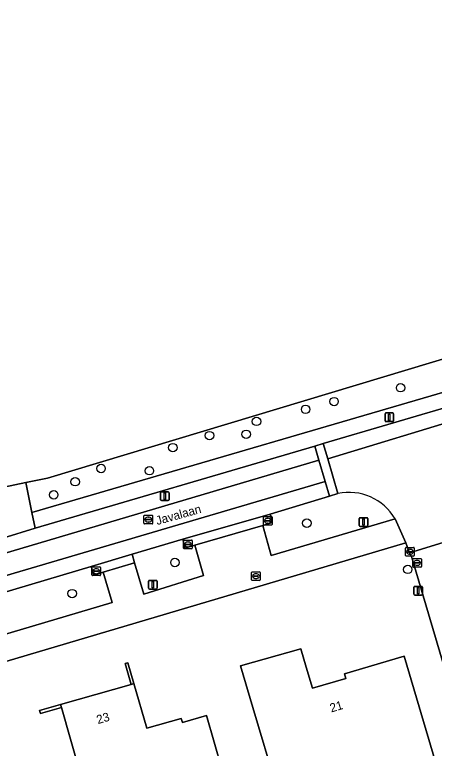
# Model space of a CAD drawing. Extents: x 162417 to 163722, y 384268 to 385417.
# Drawn here: x 163254.9 to 163303.2, y 384656 to 384740.4 of the extents above; entities that cross this region are included whole.
import ezdxf

# ---------------------------------------------------------------- set-up
doc = ezdxf.new("R2010")
doc.units = 0
for name, color, linetype in [('IMGEO_Boom', 7, 'Continuous'), ('IMGEO_Brandkraan', 7, 'Continuous'), ('IMGEO_Erf', 7, 'Continuous'), ('IMGEO_Groenvoorziening', 7, 'Continuous'), ('IMGEO_Kolk', 7, 'Continuous'), ('IMGEO_Lichtmast', 7, 'Continuous'), ('IMGEO_Muur', 7, 'Continuous'), ('IMGEO_Openbare_ruimte_label', 7, 'Continuous'), ('IMGEO_Pand', 7, 'Continuous'), ('IMGEO_Pand_nummerreeks', 7, 'Continuous'), ('IMGEO_Rijbaan_lokaal_gesloten', 7, 'Continuous'), ('IMGEO_Rijbaan_lokaal_open', 7, 'Continuous'), ('IMGEO_Rioolput', 7, 'Continuous'), ('IMGEO_Voetpad_open', 7, 'Continuous')]:
    doc.layers.add(name, color=color, linetype=linetype)

msp = doc.modelspace()

# ---------------------------------------------------------------- linework, layer by layer
at = {"layer": 'IMGEO_Boom'}
for centre in [(163299.34, 384697.477), (163291.666, 384695.87), (163288.39, 384694.985), (163282.725, 384693.6), (163281.545, 384692.108), (163277.309, 384691.956), (163273.098, 384690.574), (163264.817, 384688.168), (163270.393, 384687.917), (163261.835, 384686.655), (163259.364, 384685.138), (163288.537, 384681.888), (163273.332, 384677.355), (163300.151, 384676.563), (163261.491, 384673.768)]:
    msp.add_circle(centre, 0.489, dxfattribs=at)
at = {"layer": 'IMGEO_Brandkraan'}
for p, q in [((163282.16, 384675.355), (163282.16, 384676.207)), ((163282.235, 384676.281), (163283.087, 384676.281)), ((163282.419, 384675.775), (163282.419, 384675.787)), ((163282.857, 384675.738), (163282.459, 384675.738)), ((163282.462, 384675.824), (163282.86, 384675.824)), ((163282.648, 384676.061), (163282.673, 384676.061)), ((163282.903, 384675.787), (163282.903, 384675.775)), ((163283.161, 384676.207), (163283.161, 384675.355)), ((163283.087, 384675.281), (163282.235, 384675.281)), ((163282.671, 384675.501), (163282.646, 384675.501))]:
    msp.add_line(p, q, dxfattribs=at)
for points in [[(163282.16, 384675.355), (163282.16, 384676.207)], [(163282.235, 384676.281), (163283.087, 384676.281)], [(163283.161, 384676.207), (163283.161, 384675.355)], [(163283.087, 384675.281), (163282.235, 384675.281)]]:
    msp.add_lwpolyline(points, dxfattribs=at)
for centre, radius, start, end in [((163282.237, 384676.205), 0.0765, 91.55205, 178.44795), ((163282.237, 384676.205), 0.0765, 91.55205, 178.44795), ((163282.459, 384675.784), 0.0403, 85.87752, 175.75265), ((163282.456, 384675.774), 0.0366, 178.93798, 274.71019), ((163282.86, 384675.781), 0.043, 264.86636, 352.45326), ((163282.864, 384675.786), 0.0386, 1.73085, 96.63898), ((163283.085, 384676.205), 0.0765, 1.55205, 88.44795), ((163283.085, 384676.205), 0.0765, 1.55205, 88.44795), ((163282.237, 384675.357), 0.0765, 181.55205, 268.44795), ((163282.237, 384675.357), 0.0765, 181.55205, 268.44795), ((163283.085, 384675.357), 0.0765, 271.55205, 358.44795), ((163283.085, 384675.357), 0.0765, 271.55205, 358.44795)]:
    msp.add_arc(centre, radius, start, end, dxfattribs=at)
for centre, major_axis, ratio, start_param, end_param in [((163282.647, 384675.781), (-0.387, 0.002), 0.722429, 4.712389, 7.853982), ((163282.672, 384675.781), (-0.39, 0.002), 0.717154, 1.570796, 4.712389)]:
    msp.add_ellipse(centre, major_axis=major_axis, ratio=ratio, start_param=start_param, end_param=end_param, dxfattribs=at)
at = {"layer": 'IMGEO_Erf'}
for points in [[(163175.984, 384894.871), (163189.317, 384805.604), (163189.37, 384805.252), (163225.47, 384820.661), (163226.246, 384820.995), (163226.612, 384820.203), (163229.945, 384812.987), (163225.751, 384811.048), (163227.566, 384807.013), (163229.658, 384807.895), (163230.655, 384805.678), (163228.563, 384804.796), (163224.144, 384802.92), (163192.437, 384789.411), (163200.664, 384750), (163215.633, 384678.291), (163252.312, 384685.775), (163256.147, 384686.557), (163258.646, 384687.067), (163309.002, 384702.202), (163311.14, 384702.845), (163432.284, 384738.586)], [(163310.764, 384635.802), (163312.926, 384636.415), (163300.634, 384677.935), (163300.352, 384678.47), (163299.946, 384679.602), (163217.164, 384655.09), (163211.589, 384653.439), (163162.154, 384638.801), (163163.733, 384633.465), (163163.883, 384632.961), (163162.442, 384632.589), (163160.726, 384632.111), (163162.281, 384626.769), (163162.11, 384626.271), (163182.33, 384558.292), (163182.739, 384554.615), (163182.929, 384552.906)]]:
    msp.add_lwpolyline(points, dxfattribs=at)
for points in [[(163288.704, 384650.731), (163289.155, 384649.207), (163289.279, 384648.786), (163285.109, 384647.551), (163284.023, 384651.221), (163285.022, 384651.517), (163282.318, 384660.655), (163280.899, 384665.449), (163287.845, 384667.428), (163288.469, 384665.32), (163289.195, 384662.869), (163293.012, 384663.999), (163292.855, 384664.526), (163299.758, 384666.57), (163306.744, 384642.968), (163301.95, 384641.549), (163299.749, 384640.897), (163296.634, 384651.421), (163296.183, 384652.945)], [(163260.25, 384660.667), (163257.838, 384659.974), (163257.742, 384660.3), (163260.157, 384660.994), (163268.278, 384663.328), (163267.585, 384665.72), (163267.913, 384665.805), (163268.6, 384663.42), (163270.078, 384658.288), (163274.054, 384659.406), (163274.19, 384658.922), (163276.954, 384659.724), (163280.51, 384647.464), (163277.235, 384646.514), (163276.473, 384649.14), (163270.819, 384647.5), (163270.801, 384647.562), (163264.63, 384645.772), (163264.607, 384645.854), (163264.482, 384645.818)]]:
    msp.add_lwpolyline(points, close=True, dxfattribs=at)
at = {"layer": 'IMGEO_Groenvoorziening'}
for points in [[(163434.845, 384735.97), (163434.107, 384738.766), (163432.394, 384738.238), (163432.284, 384738.586), (163311.14, 384702.845), (163309.002, 384702.202), (163258.646, 384687.067), (163256.147, 384686.557), (163256.857, 384683.119), (163311.275, 384698.988), (163310.335, 384702.113), (163313.232, 384702.984), (163314.169, 384699.824)], [(163289.436, 384690.763), (163290.424, 384691.053), (163306.618, 384695.814), (163307.647, 384696.083), (163311.775, 384697.325), (163311.275, 384698.988), (163256.857, 384683.119), (163257.233, 384681.296)], [(163275.63, 384679.354), (163274.478, 384678.992), (163274.226, 384680.026), (163268.396, 384678.308), (163268.691, 384677.315), (163269.763, 384673.71), (163276.632, 384675.863)], [(163266.1, 384672.742), (163265.056, 384676.225), (163263.975, 384675.897), (163263.667, 384676.895), (163247.767, 384672.179), (163248.057, 384671.212), (163249.111, 384667.719)]]:
    msp.add_lwpolyline(points, close=True, dxfattribs=at)
msp.add_lwpolyline([(163292.104, 384685.298), (163291.154, 384684.983), (163284.314, 384682.93), (163284.533, 384681.94), (163283.462, 384681.623), (163284.428, 384678.165), (163298.709, 384682.365)], dxfattribs=at)
msp.add_arc((163293.368, 384679.241), 6.188, 30.32681, 101.78524, dxfattribs=at)
at = {"layer": 'IMGEO_Kolk'}
for p, q in [((163283.528, 384681.735), (163283.528, 384682.587)), ((163283.603, 384682.661), (163284.455, 384682.661)), ((163284.016, 384682.441), (163284.041, 384682.441)), ((163284.529, 384682.587), (163284.529, 384681.735)), ((163284.455, 384681.661), (163283.603, 384681.661)), ((163283.787, 384682.155), (163283.787, 384682.167)), ((163284.225, 384682.118), (163283.827, 384682.118)), ((163283.83, 384682.204), (163284.228, 384682.204)), ((163284.039, 384681.881), (163284.014, 384681.881)), ((163284.271, 384682.167), (163284.271, 384682.155)), ((163274.404, 384679.936), (163275.256, 384679.936)), ((163274.329, 384679.01), (163274.329, 384679.862)), ((163274.588, 384679.43), (163274.588, 384679.442)), ((163275.026, 384679.393), (163274.628, 384679.393)), ((163274.631, 384679.479), (163275.029, 384679.479)), ((163274.84, 384679.156), (163274.815, 384679.156)), ((163274.817, 384679.716), (163274.842, 384679.716)), ((163275.072, 384679.442), (163275.072, 384679.43)), ((163275.33, 384679.862), (163275.33, 384679.01)), ((163299.987, 384679.094), (163300.839, 384679.094)), ((163275.256, 384678.936), (163274.404, 384678.936)), ((163299.912, 384678.168), (163299.912, 384679.02)), ((163300.171, 384678.588), (163300.171, 384678.6)), ((163300.609, 384678.551), (163300.211, 384678.551)), ((163300.214, 384678.637), (163300.612, 384678.637)), ((163300.423, 384678.314), (163300.398, 384678.314)), ((163300.4, 384678.874), (163300.425, 384678.874)), ((163300.655, 384678.6), (163300.655, 384678.588)), ((163300.913, 384679.02), (163300.913, 384678.168)), ((163300.839, 384678.094), (163299.987, 384678.094)), ((163263.764, 384675.916), (163263.764, 384676.768)), ((163263.839, 384676.842), (163264.691, 384676.842)), ((163264.252, 384676.622), (163264.277, 384676.622)), ((163264.765, 384676.768), (163264.765, 384675.916)), ((163264.691, 384675.842), (163263.839, 384675.842)), ((163264.023, 384676.336), (163264.023, 384676.348)), ((163264.461, 384676.299), (163264.063, 384676.299)), ((163264.066, 384676.385), (163264.464, 384676.385)), ((163264.275, 384676.062), (163264.25, 384676.062)), ((163264.507, 384676.348), (163264.507, 384676.336))]:
    msp.add_line(p, q, dxfattribs=at)
for points in [[(163283.528, 384681.735), (163283.528, 384682.587)], [(163283.603, 384682.661), (163284.455, 384682.661)], [(163284.529, 384682.587), (163284.529, 384681.735)], [(163284.455, 384681.661), (163283.603, 384681.661)], [(163274.404, 384679.936), (163275.256, 384679.936)], [(163274.329, 384679.01), (163274.329, 384679.862)], [(163275.33, 384679.862), (163275.33, 384679.01)], [(163299.987, 384679.094), (163300.839, 384679.094)], [(163275.256, 384678.936), (163274.404, 384678.936)], [(163299.912, 384678.168), (163299.912, 384679.02)], [(163300.913, 384679.02), (163300.913, 384678.168)], [(163300.839, 384678.094), (163299.987, 384678.094)], [(163263.764, 384675.916), (163263.764, 384676.768)], [(163263.839, 384676.842), (163264.691, 384676.842)], [(163264.765, 384676.768), (163264.765, 384675.916)], [(163264.691, 384675.842), (163263.839, 384675.842)]]:
    msp.add_lwpolyline(points, dxfattribs=at)
for centre, radius, start, end in [((163283.605, 384682.585), 0.0765, 91.55205, 178.44795), ((163283.605, 384682.585), 0.0765, 91.55205, 178.44795), ((163284.453, 384682.585), 0.0765, 1.55205, 88.44795), ((163284.453, 384682.585), 0.0765, 1.55205, 88.44795), ((163283.605, 384681.737), 0.0765, 181.55205, 268.44795), ((163283.605, 384681.737), 0.0765, 181.55205, 268.44795), ((163283.827, 384682.164), 0.0403, 85.87752, 175.75265), ((163283.824, 384682.154), 0.0366, 178.93798, 274.71019), ((163284.228, 384682.161), 0.043, 264.86636, 352.45326), ((163284.232, 384682.166), 0.0386, 1.73085, 96.63898), ((163284.453, 384681.737), 0.0765, 271.55205, 358.44795), ((163284.453, 384681.737), 0.0765, 271.55205, 358.44795), ((163274.406, 384679.86), 0.0765, 91.55205, 178.44795), ((163274.406, 384679.86), 0.0765, 91.55205, 178.44795), ((163275.254, 384679.86), 0.0765, 1.55205, 88.44795), ((163275.254, 384679.86), 0.0765, 1.55205, 88.44795), ((163274.628, 384679.439), 0.0403, 85.87752, 175.75265), ((163274.625, 384679.429), 0.0366, 178.93798, 274.71019), ((163275.029, 384679.436), 0.043, 264.86636, 352.45326), ((163275.033, 384679.441), 0.0386, 1.73085, 96.63898), ((163299.989, 384679.018), 0.0765, 91.55205, 178.44795), ((163299.989, 384679.018), 0.0765, 91.55205, 178.44795), ((163300.837, 384679.018), 0.0765, 1.55205, 88.44795), ((163300.837, 384679.018), 0.0765, 1.55205, 88.44795), ((163274.406, 384679.012), 0.0765, 181.55205, 268.44795), ((163274.406, 384679.012), 0.0765, 181.55205, 268.44795), ((163275.254, 384679.012), 0.0765, 271.55205, 358.44795), ((163275.254, 384679.012), 0.0765, 271.55205, 358.44795), ((163300.211, 384678.597), 0.0403, 85.87752, 175.75265), ((163300.208, 384678.587), 0.0366, 178.93798, 274.71019), ((163300.612, 384678.594), 0.043, 264.86636, 352.45326), ((163300.616, 384678.599), 0.0386, 1.73085, 96.63898), ((163299.989, 384678.17), 0.0765, 181.55205, 268.44795), ((163299.989, 384678.17), 0.0765, 181.55205, 268.44795), ((163300.837, 384678.17), 0.0765, 271.55205, 358.44795), ((163300.837, 384678.17), 0.0765, 271.55205, 358.44795), ((163263.841, 384676.766), 0.0765, 91.55205, 178.44795), ((163263.841, 384676.766), 0.0765, 91.55205, 178.44795), ((163264.689, 384676.766), 0.0765, 1.55205, 88.44795), ((163264.689, 384676.766), 0.0765, 1.55205, 88.44795), ((163263.841, 384675.918), 0.0765, 181.55205, 268.44795), ((163263.841, 384675.918), 0.0765, 181.55205, 268.44795), ((163264.063, 384676.345), 0.0403, 85.87752, 175.75265), ((163264.06, 384676.335), 0.0366, 178.93798, 274.71019), ((163264.464, 384676.342), 0.043, 264.86636, 352.45326), ((163264.468, 384676.347), 0.0386, 1.73085, 96.63898), ((163264.689, 384675.918), 0.0765, 271.55205, 358.44795), ((163264.689, 384675.918), 0.0765, 271.55205, 358.44795)]:
    msp.add_arc(centre, radius, start, end, dxfattribs=at)
for centre, major_axis, ratio, start_param, end_param in [((163284.015, 384682.161), (-0.387, 0.002), 0.722429, 4.712389, 7.853982), ((163284.04, 384682.161), (-0.39, 0.002), 0.717154, 1.570796, 4.712389), ((163274.816, 384679.436), (-0.387, 0.002), 0.722429, 4.712389, 7.853982), ((163274.841, 384679.436), (-0.39, 0.002), 0.717154, 1.570796, 4.712389), ((163300.399, 384678.594), (-0.387, 0.002), 0.722429, 4.712389, 7.853982), ((163300.424, 384678.594), (-0.39, 0.002), 0.717154, 1.570796, 4.712389), ((163264.251, 384676.342), (-0.387, 0.002), 0.722429, 4.712389, 7.853982), ((163264.276, 384676.342), (-0.39, 0.002), 0.717154, 1.570796, 4.712389)]:
    msp.add_ellipse(centre, major_axis=major_axis, ratio=ratio, start_param=start_param, end_param=end_param, dxfattribs=at)
at = {"layer": 'IMGEO_Lichtmast'}
for p, q in [((163297.537, 384693.672), (163297.537, 384694.472)), ((163297.537, 384694.472), (163297.537, 384693.672)), ((163297.637, 384694.572), (163298.427, 384694.572)), ((163298.427, 384694.572), (163297.637, 384694.572)), ((163298.527, 384694.472), (163298.527, 384693.672)), ((163298.527, 384693.672), (163298.527, 384694.472)), ((163298.427, 384693.572), (163297.637, 384693.572)), ((163297.637, 384693.572), (163298.427, 384693.572)), ((163271.667, 384684.583), (163271.667, 384685.383)), ((163271.667, 384685.383), (163271.667, 384684.583)), ((163271.767, 384685.483), (163272.557, 384685.483)), ((163272.557, 384685.483), (163271.767, 384685.483)), ((163272.657, 384685.383), (163272.657, 384684.583)), ((163272.657, 384684.583), (163272.657, 384685.383)), ((163272.557, 384684.483), (163271.767, 384684.483)), ((163271.767, 384684.483), (163272.557, 384684.483)), ((163294.677, 384682.511), (163295.467, 384682.511)), ((163295.467, 384682.511), (163294.677, 384682.511)), ((163294.577, 384681.611), (163294.577, 384682.411)), ((163294.577, 384682.411), (163294.577, 384681.611)), ((163295.567, 384682.411), (163295.567, 384681.611)), ((163295.567, 384681.611), (163295.567, 384682.411)), ((163295.467, 384681.511), (163294.677, 384681.511)), ((163294.677, 384681.511), (163295.467, 384681.511)), ((163270.293, 384674.4), (163270.293, 384675.2)), ((163270.293, 384675.2), (163270.293, 384674.4)), ((163270.393, 384675.3), (163271.183, 384675.3)), ((163271.183, 384675.3), (163270.393, 384675.3)), ((163271.283, 384675.2), (163271.283, 384674.4)), ((163271.283, 384674.4), (163271.283, 384675.2)), ((163271.183, 384674.3), (163270.393, 384674.3)), ((163270.393, 384674.3), (163271.183, 384674.3)), ((163300.87, 384673.709), (163300.87, 384674.509)), ((163300.87, 384674.509), (163300.87, 384673.709)), ((163300.97, 384674.609), (163301.76, 384674.609)), ((163301.76, 384674.609), (163300.97, 384674.609)), ((163301.86, 384674.509), (163301.86, 384673.709)), ((163301.86, 384673.709), (163301.86, 384674.509)), ((163301.76, 384673.609), (163300.97, 384673.609)), ((163300.97, 384673.609), (163301.76, 384673.609))]:
    msp.add_line(p, q, dxfattribs=at)
for points in [[(163297.957, 384694.447), (163298.107, 384694.447), (163298.107, 384693.697), (163297.957, 384693.697), (163297.957, 384694.447)], [(163272.087, 384685.358), (163272.237, 384685.358), (163272.237, 384684.608), (163272.087, 384684.608), (163272.087, 384685.358)], [(163294.997, 384682.386), (163295.147, 384682.386), (163295.147, 384681.636), (163294.997, 384681.636), (163294.997, 384682.386)], [(163270.713, 384675.175), (163270.863, 384675.175), (163270.863, 384674.425), (163270.713, 384674.425), (163270.713, 384675.175)], [(163301.29, 384674.484), (163301.44, 384674.484), (163301.44, 384673.734), (163301.29, 384673.734), (163301.29, 384674.484)]]:
    msp.add_lwpolyline(points, dxfattribs=at)
for centre, start, end in [((163297.637, 384694.472), 90, 180), ((163297.637, 384694.472), 90, 180), ((163298.427, 384694.472), 0, 90), ((163298.427, 384694.472), 360, 90), ((163297.637, 384693.672), 180, 270), ((163297.637, 384693.672), 180, 270), ((163298.427, 384693.672), 270, 0), ((163298.427, 384693.672), 270, 0), ((163271.767, 384685.383), 90, 180), ((163271.767, 384685.383), 90, 180), ((163272.557, 384685.383), 0, 90), ((163272.557, 384685.383), 360, 90), ((163271.767, 384684.583), 180, 270), ((163271.767, 384684.583), 180, 270), ((163272.557, 384684.583), 270, 0), ((163272.557, 384684.583), 270, 0), ((163294.677, 384682.411), 90, 180), ((163294.677, 384682.411), 90, 180), ((163295.467, 384682.411), 0, 90), ((163295.467, 384682.411), 360, 90), ((163294.677, 384681.611), 180, 270), ((163294.677, 384681.611), 180, 270), ((163295.467, 384681.611), 270, 0), ((163295.467, 384681.611), 270, 0), ((163270.393, 384675.2), 90, 180), ((163270.393, 384675.2), 90, 180), ((163271.183, 384675.2), 0, 90), ((163271.183, 384675.2), 360, 90), ((163270.393, 384674.4), 180, 270), ((163270.393, 384674.4), 180, 270), ((163271.183, 384674.4), 270, 0), ((163271.183, 384674.4), 270, 0), ((163300.97, 384674.509), 90, 180), ((163300.97, 384674.509), 90, 180), ((163301.76, 384674.509), 0, 90), ((163301.76, 384674.509), 360, 90), ((163300.97, 384673.709), 180, 270), ((163300.97, 384673.709), 180, 270), ((163301.76, 384673.709), 270, 0), ((163301.76, 384673.709), 270, 0)]:
    msp.add_arc(centre, 0.1, start, end, dxfattribs=at)
at = {"layer": 'IMGEO_Muur'}
for points in [[(163268.278, 384663.328), (163268.6, 384663.42), (163267.913, 384665.805), (163267.585, 384665.72)], [(163260.157, 384660.994), (163257.742, 384660.3), (163257.838, 384659.974), (163260.25, 384660.667)]]:
    msp.add_lwpolyline(points, close=True, dxfattribs=at)
at = {"layer": 'IMGEO_Pand'}
for points in [[(163288.704, 384650.731), (163296.183, 384652.945), (163296.634, 384651.421), (163299.749, 384640.897), (163301.95, 384641.549), (163306.744, 384642.968), (163299.758, 384666.57), (163292.855, 384664.526), (163293.012, 384663.999), (163289.195, 384662.869), (163288.469, 384665.32), (163287.845, 384667.428), (163280.899, 384665.449), (163282.318, 384660.655), (163285.022, 384651.517), (163284.023, 384651.221), (163285.109, 384647.551), (163289.279, 384648.786), (163289.155, 384649.207)], [(163276.954, 384659.724), (163274.19, 384658.922), (163274.054, 384659.406), (163270.078, 384658.288), (163268.6, 384663.42), (163268.278, 384663.328), (163260.157, 384660.994), (163260.25, 384660.667), (163264.482, 384645.818), (163264.607, 384645.854), (163264.63, 384645.772), (163270.801, 384647.562), (163270.819, 384647.5), (163276.473, 384649.14), (163277.235, 384646.514), (163280.51, 384647.464)]]:
    msp.add_lwpolyline(points, close=True, dxfattribs=at)
at = {"layer": 'IMGEO_Rijbaan_lokaal_gesloten'}
for points in [[(163290.424, 384691.053), (163290.945, 384689.301), (163307.122, 384694.182), (163306.618, 384695.814)], [(163257.233, 384681.296), (163253.504, 384680.159), (163217.379, 384669.518), (163217.858, 384667.814), (163289.922, 384689.131), (163289.436, 384690.763)], [(163219.046, 384663.763), (163243.04, 384670.847), (163247.767, 384672.179), (163263.667, 384676.895), (163268.396, 384678.308), (163274.226, 384680.026), (163284.314, 384682.93), (163291.154, 384684.983), (163290.633, 384686.675), (163218.569, 384665.465)]]:
    msp.add_lwpolyline(points, close=True, dxfattribs=at)
at = {"layer": 'IMGEO_Rijbaan_lokaal_open'}
for points in [[(163308.357, 384690.004), (163307.122, 384694.182), (163290.945, 384689.301), (163292.104, 384685.298)], [(163298.709, 384682.365), (163299.946, 384679.602), (163300.352, 384678.47), (163305.248, 384679.964), (163304.927, 384681.002), (163304.395, 384682.827), (163304.239, 384683.939)], [(163322.986, 384620.355), (163322.7, 384621.313), (163321.795, 384624.338), (163321.537, 384625.199), (163317.662, 384638.152), (163313.725, 384651.399), (163311.404, 384659.211), (163306.588, 384675.415), (163305.445, 384679.26), (163305.248, 384679.964), (163300.352, 384678.47), (163300.634, 384677.935), (163312.926, 384636.415), (163317.237, 384621.888), (163323.475, 384600.863), (163323.936, 384598.792), (163323.763, 384596.699)]]:
    msp.add_lwpolyline(points, dxfattribs=at)
for points in [[(163290.424, 384691.053), (163289.436, 384690.763), (163289.922, 384689.131), (163290.633, 384686.675), (163291.154, 384684.983), (163292.104, 384685.298), (163290.945, 384689.301)], [(163218.569, 384665.465), (163290.633, 384686.675), (163289.922, 384689.131), (163217.858, 384667.814)]]:
    msp.add_lwpolyline(points, close=True, dxfattribs=at)
msp.add_arc((163293.368, 384679.241), 6.188, 30.32681, 101.78524, dxfattribs=at)
at = {"layer": 'IMGEO_Rioolput'}
for p, q in [((163269.767, 384681.865), (163269.767, 384682.717)), ((163269.842, 384682.791), (163270.694, 384682.791)), ((163270.255, 384682.571), (163270.28, 384682.571)), ((163270.768, 384682.717), (163270.768, 384681.865)), ((163270.694, 384681.791), (163269.842, 384681.791)), ((163270.026, 384682.285), (163270.026, 384682.297)), ((163270.464, 384682.248), (163270.066, 384682.248)), ((163270.069, 384682.334), (163270.467, 384682.334)), ((163270.278, 384682.011), (163270.253, 384682.011)), ((163270.51, 384682.297), (163270.51, 384682.285)), ((163300.727, 384676.881), (163300.727, 384677.733)), ((163300.802, 384677.807), (163301.654, 384677.807)), ((163301.215, 384677.587), (163301.24, 384677.587)), ((163301.728, 384677.733), (163301.728, 384676.881)), ((163301.654, 384676.807), (163300.802, 384676.807)), ((163300.986, 384677.301), (163300.986, 384677.313)), ((163301.424, 384677.264), (163301.026, 384677.264)), ((163301.029, 384677.35), (163301.427, 384677.35)), ((163301.238, 384677.027), (163301.213, 384677.027)), ((163301.47, 384677.313), (163301.47, 384677.301))]:
    msp.add_line(p, q, dxfattribs=at)
for points in [[(163269.767, 384681.865), (163269.767, 384682.717)], [(163269.842, 384682.791), (163270.694, 384682.791)], [(163270.768, 384682.717), (163270.768, 384681.865)], [(163270.694, 384681.791), (163269.842, 384681.791)], [(163300.727, 384676.881), (163300.727, 384677.733)], [(163300.802, 384677.807), (163301.654, 384677.807)], [(163301.728, 384677.733), (163301.728, 384676.881)], [(163301.654, 384676.807), (163300.802, 384676.807)]]:
    msp.add_lwpolyline(points, dxfattribs=at)
for centre, radius, start, end in [((163269.844, 384682.715), 0.0765, 91.55205, 178.44795), ((163269.844, 384682.715), 0.0765, 91.55205, 178.44795), ((163270.692, 384682.715), 0.0765, 1.55205, 88.44795), ((163270.692, 384682.715), 0.0765, 1.55205, 88.44795), ((163269.844, 384681.867), 0.0765, 181.55205, 268.44795), ((163269.844, 384681.867), 0.0765, 181.55205, 268.44795), ((163270.066, 384682.294), 0.0403, 85.87752, 175.75265), ((163270.063, 384682.284), 0.0366, 178.93798, 274.71019), ((163270.467, 384682.291), 0.043, 264.86636, 352.45326), ((163270.471, 384682.296), 0.0386, 1.73085, 96.63898), ((163270.692, 384681.867), 0.0765, 271.55205, 358.44795), ((163270.692, 384681.867), 0.0765, 271.55205, 358.44795), ((163300.804, 384677.731), 0.0765, 91.55205, 178.44795), ((163300.804, 384677.731), 0.0765, 91.55205, 178.44795), ((163301.652, 384677.731), 0.0765, 1.55205, 88.44795), ((163301.652, 384677.731), 0.0765, 1.55205, 88.44795), ((163300.804, 384676.883), 0.0765, 181.55205, 268.44795), ((163300.804, 384676.883), 0.0765, 181.55205, 268.44795), ((163301.026, 384677.31), 0.0403, 85.87752, 175.75265), ((163301.023, 384677.3), 0.0366, 178.93798, 274.71019), ((163301.427, 384677.307), 0.043, 264.86636, 352.45326), ((163301.431, 384677.312), 0.0386, 1.73085, 96.63898), ((163301.652, 384676.883), 0.0765, 271.55205, 358.44795), ((163301.652, 384676.883), 0.0765, 271.55205, 358.44795)]:
    msp.add_arc(centre, radius, start, end, dxfattribs=at)
for centre, major_axis, ratio, start_param, end_param in [((163270.254, 384682.291), (-0.387, 0.002), 0.722429, 4.712389, 7.853982), ((163270.279, 384682.291), (-0.39, 0.002), 0.717154, 1.570796, 4.712389), ((163301.214, 384677.307), (-0.387, 0.002), 0.722429, 4.712389, 7.853982), ((163301.239, 384677.307), (-0.39, 0.002), 0.717154, 1.570796, 4.712389)]:
    msp.add_ellipse(centre, major_axis=major_axis, ratio=ratio, start_param=start_param, end_param=end_param, dxfattribs=at)
at = {"layer": 'IMGEO_Voetpad_open'}
for points in [[(163256.147, 384686.557), (163252.312, 384685.775), (163252.434, 384685.061), (163253.099, 384682.014), (163253.504, 384680.159), (163257.233, 384681.296), (163256.857, 384683.119)], [(163283.462, 384681.623), (163284.533, 384681.94), (163284.314, 384682.93), (163274.226, 384680.026), (163274.478, 384678.992), (163275.63, 384679.354)], [(163265.056, 384676.225), (163268.691, 384677.315), (163268.396, 384678.308), (163263.667, 384676.895), (163263.975, 384675.897)]]:
    msp.add_lwpolyline(points, close=True, dxfattribs=at)
msp.add_lwpolyline([(163217.164, 384655.09), (163299.946, 384679.602), (163298.709, 384682.365), (163284.428, 384678.165), (163283.462, 384681.623), (163275.63, 384679.354), (163276.632, 384675.863), (163269.763, 384673.71), (163268.691, 384677.315), (163265.056, 384676.225), (163266.1, 384672.742), (163249.111, 384667.719)], dxfattribs=at)

# ---------------------------------------------------------------- texts
at = {"layer": 'IMGEO_Openbare_ruimte_label'}
msp.add_text('Javalaan', height=1, rotation=15.42597, dxfattribs=at).set_placement((163271.283, 384681.661))
at = {"layer": 'IMGEO_Pand_nummerreeks'}
for s, rotation, p in [('21', 16.49107, (163291.351, 384660.086)), ('23', 16.48973, (163264.468, 384658.745))]:
    msp.add_text(s, height=1, rotation=rotation, dxfattribs=at).set_placement(p)

doc.saveas('drawing.dxf')
